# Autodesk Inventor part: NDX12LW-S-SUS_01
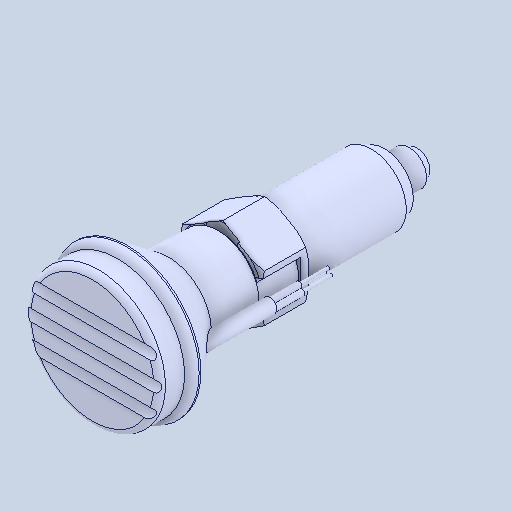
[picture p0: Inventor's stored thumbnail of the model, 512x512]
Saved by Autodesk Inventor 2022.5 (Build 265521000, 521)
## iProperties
Created: 2024-05
Part Number: NDX12LW-S-SUS_01
Material: 一般
Document SubType Name: Modeling
Designer: ImaoCorp
Density: 1 g/cm^3
Appearance: 既定
Author: ImaoCorp
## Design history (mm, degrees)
feature "NDX12LW-S-SUS_01"
node "ソリッド1"
